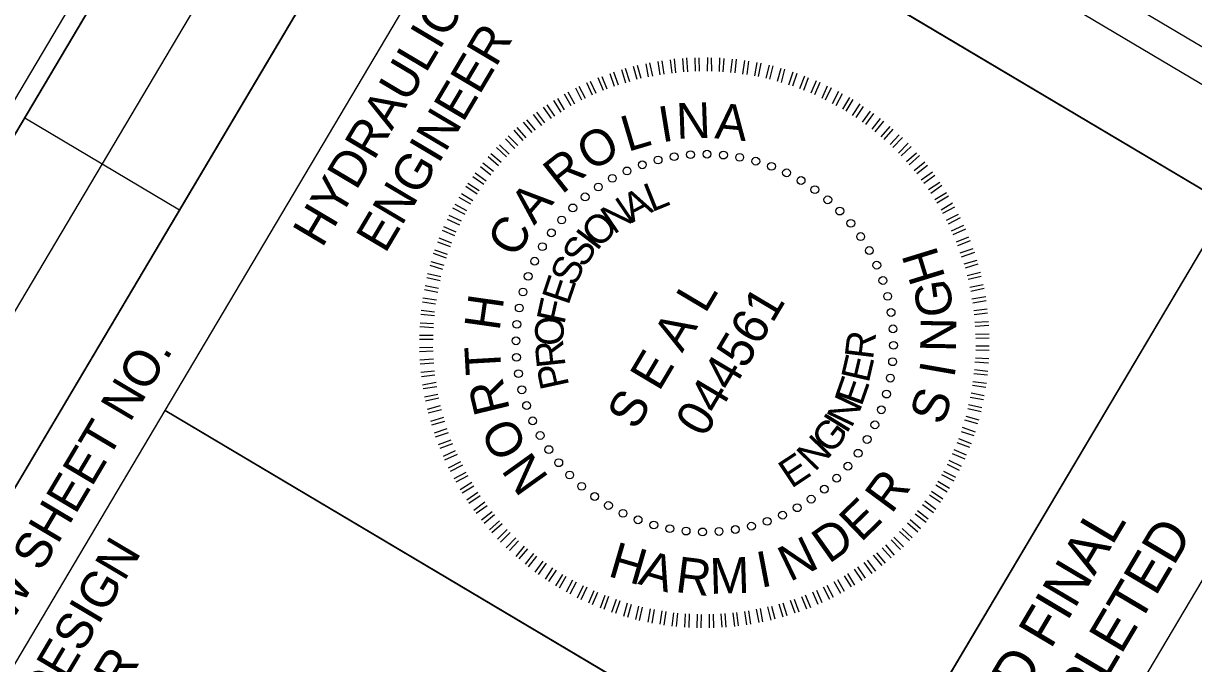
# Model space of a CAD drawing. Extents: x 2137081 to 2142019, y 404041 to 411238.
# Drawn here: x 2141049.2 to 2141211.9, y 410874.6 to 410963.6 of the extents above; entities that cross this region are included whole.
import ezdxf

# ---------------------------------------------------------------- set-up
doc = ezdxf.new("R2010")
doc.units = 0
for name, color, linetype in [('Old_Level_2', 7, 'Continuous'), ('Sheet Clip Boundary CELL', 7, 'Continuous'), ('Sheet Plan And Profile CELL', 7, 'Continuous'), ('Sheet Plot Border Inside CELL', 7, 'Continuous'), ('Sheet Plot Border Outside CELL', 7, 'Continuous'), ('Sheet Sticker Exception Certification CELL', 7, 'Continuous')]:
    doc.layers.add(name, color=color, linetype=linetype)

msp = doc.modelspace()

# ---------------------------------------------------------------- linework, layer by layer
at = {"layer": 'Old_Level_2'}
for p, q in [((2141137.73, 410956.43), (2141137.44, 410958.28)), ((2141138.28, 410956.5), (2141137.98, 410958.34)), ((2141139.36, 410956.63), (2141139.13, 410958.5)), ((2141139.9, 410956.7), (2141139.7, 410958.61)), ((2141140.99, 410956.84), (2141140.86, 410958.7)), ((2141141.54, 410956.84), (2141141.4, 410958.76)), ((2141142.64, 410956.91), (2141142.59, 410958.79)), ((2141143.2, 410956.91), (2141143.15, 410958.79)), ((2141144.28, 410956.94), (2141144.33, 410958.81)), ((2141144.88, 410956.92), (2141144.86, 410958.77)), ((2141145.95, 410956.85), (2141146.02, 410958.75)), ((2141146.48, 410956.81), (2141146.6, 410958.69)), ((2141147.55, 410956.73), (2141147.77, 410958.6)), ((2141148.13, 410956.67), (2141148.31, 410958.57)), ((2141149.21, 410956.52), (2141149.5, 410958.42)), ((2141149.79, 410956.46), (2141150.05, 410958.31)), ((2141150.85, 410956.28), (2141151.18, 410958.14)), ((2141131.36, 410954.8), (2141130.74, 410956.57)), ((2141131.91, 410954.98), (2141131.25, 410956.77)), ((2141132.92, 410955.27), (2141132.39, 410957.09)), ((2141133.47, 410955.45), (2141132.9, 410957.29)), ((2141134.51, 410955.78), (2141134.01, 410957.58)), ((2141135.07, 410955.89), (2141134.58, 410957.69)), ((2141136.1, 410956.12), (2141135.74, 410957.95)), ((2141136.67, 410956.23), (2141136.26, 410958.08)), ((2141151.4, 410956.17), (2141151.73, 410958.04)), ((2141152.44, 410955.95), (2141152.89, 410957.74)), ((2141152.96, 410955.8), (2141153.44, 410957.64)), ((2141154.02, 410955.51), (2141154.53, 410957.32)), ((2141154.58, 410955.34), (2141155.06, 410957.18)), ((2141155.61, 410955.01), (2141156.19, 410956.84)), ((2141156.14, 410954.86), (2141156.74, 410956.63)), ((2141128.29, 410953.57), (2141127.53, 410955.3)), ((2141128.82, 410953.81), (2141128.04, 410955.5)), ((2141129.84, 410954.21), (2141129.11, 410955.98)), ((2141130.35, 410954.41), (2141129.66, 410956.15)), ((2141157.14, 410954.49), (2141157.81, 410956.27)), ((2141157.69, 410954.28), (2141158.35, 410956.06)), ((2141158.69, 410953.91), (2141159.44, 410955.64)), ((2141159.21, 410953.66), (2141159.96, 410955.38)), ((2141160.21, 410953.18), (2141160.99, 410954.88)), ((2141125.35, 410952.08), (2141124.43, 410953.74)), ((2141125.84, 410952.35), (2141124.93, 410954)), ((2141126.82, 410952.88), (2141125.98, 410954.55)), ((2141127.35, 410953.12), (2141126.47, 410954.81)), ((2141160.68, 410952.95), (2141161.54, 410954.67)), ((2141161.66, 410952.43), (2141162.55, 410954.12)), ((2141162.17, 410952.17), (2141163.05, 410953.83)), ((2141163.08, 410951.64), (2141164.06, 410953.28)), ((2141122.58, 410950.33), (2141121.51, 410951.91)), ((2141123.05, 410950.66), (2141121.99, 410952.24)), ((2141123.95, 410951.24), (2141122.95, 410952.83)), ((2141124.4, 410951.53), (2141123.47, 410953.14)), ((2141163.57, 410951.34), (2141164.55, 410952.99)), ((2141164.46, 410950.76), (2141165.52, 410952.36)), ((2141164.95, 410950.47), (2141165.99, 410952.03)), ((2141120.4, 410948.72), (2141119.19, 410950.16)), ((2141121.24, 410949.39), (2141120.09, 410950.91)), ((2141121.68, 410949.75), (2141120.56, 410951.24)), ((2141165.85, 410949.82), (2141166.93, 410951.36)), ((2141166.28, 410949.51), (2141167.4, 410951.02)), ((2141167.18, 410948.87), (2141168.34, 410950.35)), ((2141167.62, 410948.49), (2141168.78, 410949.98)), ((2141118.66, 410947.3), (2141117.43, 410948.7)), ((2141119.1, 410947.65), (2141117.83, 410949.08)), ((2141119.92, 410948.39), (2141118.72, 410949.83)), ((2141168.43, 410947.79), (2141169.67, 410949.23)), ((2141168.84, 410947.44), (2141170.08, 410948.88)), ((2141117.49, 410946.16), (2141116.19, 410947.54)), ((2141117.9, 410946.58), (2141116.58, 410947.92)), ((2141169.69, 410946.71), (2141170.94, 410948.08)), ((2141170.07, 410946.32), (2141171.39, 410947.71)), ((2141170.83, 410945.53), (2141172.19, 410946.9)), ((2141115.61, 410944.21), (2141114.17, 410945.45)), ((2141116.35, 410945), (2141114.96, 410946.32)), ((2141116.7, 410945.4), (2141115.36, 410946.7)), ((2141171.2, 410945.14), (2141172.59, 410946.44)), ((2141171.96, 410944.36), (2141173.36, 410945.59)), ((2141172.32, 410943.92), (2141173.74, 410945.2)), ((2141114.19, 410942.49), (2141112.71, 410943.65)), ((2141114.53, 410942.96), (2141113.04, 410944.12)), ((2141115.23, 410943.77), (2141113.79, 410945.01)), ((2141173.01, 410943.12), (2141174.5, 410944.3)), ((2141173.37, 410942.69), (2141174.85, 410943.87)), ((2141113.2, 410941.18), (2141111.66, 410942.26)), ((2141113.53, 410941.65), (2141112, 410942.73)), ((2141174.01, 410941.8), (2141175.58, 410942.94)), ((2141174.37, 410941.37), (2141175.87, 410942.49)), ((2141112.28, 410939.83), (2141110.68, 410940.89)), ((2141112.55, 410940.29), (2141110.99, 410941.32)), ((2141175.02, 410940.49), (2141176.57, 410941.51)), ((2141175.32, 410939.97), (2141176.86, 410941.06)), ((2141111.39, 410938.42), (2141109.78, 410939.37)), ((2141111.68, 410938.91), (2141110.07, 410939.86)), ((2141175.9, 410939.07), (2141177.5, 410940.07)), ((2141176.19, 410938.62), (2141177.79, 410939.62)), ((2141176.75, 410937.67), (2141178.36, 410938.61)), ((2141110.6, 410936.99), (2141108.9, 410937.89)), ((2141110.85, 410937.51), (2141109.19, 410938.38)), ((2141177.01, 410937.18), (2141178.67, 410938.09)), ((2141177.5, 410936.22), (2141179.17, 410937.07)), ((2141109.85, 410935.54), (2141108.14, 410936.33)), ((2141110.1, 410936.06), (2141108.39, 410936.85)), ((2141177.77, 410935.73), (2141179.44, 410936.58)), ((2141178.23, 410934.73), (2141179.92, 410935.51)), ((2141108.74, 410933.02), (2141106.99, 410933.73)), ((2141109.18, 410934.04), (2141107.45, 410934.79)), ((2141109.37, 410934.54), (2141107.64, 410935.29)), ((2141178.43, 410934.22), (2141180.18, 410935.02)), ((2141178.9, 410933.22), (2141180.64, 410933.91)), ((2141108.55, 410932.52), (2141106.78, 410933.18)), ((2141179.09, 410932.71), (2141180.84, 410933.41)), ((2141179.43, 410931.68), (2141181.23, 410932.28)), ((2141108.01, 410930.95), (2141106.21, 410931.57)), ((2141108.16, 410931.47), (2141106.4, 410932.07)), ((2141179.6, 410931.13), (2141181.43, 410931.77)), ((2141179.96, 410930.14), (2141181.78, 410930.67)), ((2141107.51, 410929.35), (2141105.72, 410929.91)), ((2141107.68, 410929.92), (2141105.87, 410930.44)), ((2141180.14, 410929.59), (2141181.92, 410930.15)), ((2141180.4, 410928.54), (2141182.24, 410929.01)), ((2141107.14, 410927.79), (2141105.28, 410928.22)), ((2141107.24, 410928.34), (2141105.38, 410928.77)), ((2141180.54, 410928.01), (2141182.35, 410928.44)), ((2141180.78, 410926.92), (2141182.61, 410927.28)), ((2141106.79, 410926.16), (2141104.94, 410926.53)), ((2141106.89, 410926.71), (2141105.05, 410927.08)), ((2141180.89, 410926.36), (2141182.75, 410926.76)), ((2141181.05, 410925.31), (2141182.97, 410925.63)), ((2141106.5, 410924.55), (2141104.65, 410924.81)), ((2141106.6, 410925.1), (2141104.71, 410925.38)), ((2141181.16, 410924.75), (2141183.03, 410925.08)), ((2141106.32, 410922.93), (2141104.42, 410923.11)), ((2141106.35, 410923.46), (2141104.48, 410923.68)), ((2141181.3, 410923.66), (2141183.16, 410923.89)), ((2141181.37, 410923.12), (2141183.23, 410923.35)), ((2141106.18, 410921.28), (2141104.29, 410921.4)), ((2141106.21, 410921.82), (2141104.33, 410921.93)), ((2141181.46, 410922.06), (2141183.36, 410922.16)), ((2141181.51, 410921.48), (2141183.39, 410921.64)), ((2141106.14, 410920.19), (2141104.25, 410920.2)), ((2141106.14, 410919.63), (2141104.25, 410919.64)), ((2141181.54, 410920.4), (2141183.45, 410920.44)), ((2141181.58, 410919.82), (2141183.45, 410919.88)), ((2141106.11, 410918.54), (2141104.23, 410918.48)), ((2141106.17, 410918), (2141104.24, 410917.92)), ((2141181.57, 410918.77), (2141183.46, 410918.76)), ((2141181.57, 410918.21), (2141183.44, 410918.16)), ((2141106.2, 410916.92), (2141104.32, 410916.75)), ((2141106.25, 410916.34), (2141104.33, 410916.2)), ((2141181.47, 410916.54), (2141183.35, 410916.42)), ((2141181.54, 410917.11), (2141183.42, 410917)), ((2141106.32, 410915.24), (2141104.44, 410915.07)), ((2141106.39, 410914.69), (2141104.52, 410914.46)), ((2141181.33, 410914.9), (2141183.23, 410914.72)), ((2141181.4, 410915.47), (2141183.27, 410915.25)), ((2141106.55, 410913.65), (2141104.68, 410913.31)), ((2141106.66, 410913.08), (2141104.75, 410912.77)), ((2141181.11, 410913.3), (2141183, 410913.01)), ((2141181.19, 410913.81), (2141183.06, 410913.59)), ((2141106.8, 410912), (2141104.96, 410911.64)), ((2141106.93, 410911.48), (2141105.07, 410911.07)), ((2141180.8, 410911.65), (2141182.66, 410911.32)), ((2141180.93, 410912.24), (2141182.77, 410911.87)), ((2141107.13, 410910.41), (2141105.33, 410909.92)), ((2141107.31, 410909.86), (2141105.47, 410909.39)), ((2141180.47, 410910.06), (2141182.33, 410909.62)), ((2141180.57, 410910.61), (2141182.43, 410910.18)), ((2141107.57, 410908.81), (2141105.79, 410908.25)), ((2141107.75, 410908.26), (2141105.93, 410907.72)), ((2141180.03, 410908.48), (2141181.84, 410907.96)), ((2141180.18, 410909.01), (2141181.99, 410908.49)), ((2141108.04, 410907.25), (2141106.28, 410906.62)), ((2141108.26, 410906.68), (2141106.45, 410906.08)), ((2141179.53, 410906.88), (2141181.32, 410906.32)), ((2141179.7, 410907.45), (2141181.5, 410906.83)), ((2141108.62, 410905.68), (2141106.87, 410904.99)), ((2141108.82, 410905.17), (2141107.07, 410904.48)), ((2141178.95, 410905.34), (2141180.72, 410904.67)), ((2141179.16, 410905.88), (2141180.93, 410905.21)), ((2141109.22, 410904.16), (2141107.53, 410903.38)), ((2141109.48, 410903.67), (2141107.73, 410902.87)), ((2141177.86, 410902.86), (2141179.54, 410902.03)), ((2141178.32, 410903.81), (2141180.05, 410903.07)), ((2141178.53, 410904.36), (2141180.26, 410903.61)), ((2141109.95, 410902.67), (2141108.25, 410901.78)), ((2141110.21, 410902.17), (2141108.51, 410901.29)), ((2141110.68, 410901.17), (2141109.04, 410900.3)), ((2141177.09, 410901.37), (2141178.75, 410900.5)), ((2141177.61, 410902.34), (2141179.29, 410901.51)), ((2141110.97, 410900.72), (2141109.31, 410899.81)), ((2141111.52, 410899.78), (2141109.92, 410898.78)), ((2141176.3, 410899.94), (2141177.91, 410898.99)), ((2141176.82, 410900.91), (2141178.52, 410900.02)), ((2141111.79, 410899.29), (2141110.19, 410898.29)), ((2141112.37, 410898.39), (2141110.83, 410897.3)), ((2141175.13, 410898.07), (2141176.69, 410897.03)), ((2141175.43, 410898.56), (2141176.99, 410897.53)), ((2141176.01, 410899.45), (2141177.61, 410898.49)), ((2141112.7, 410897.91), (2141111.12, 410896.85)), ((2141113.34, 410897.03), (2141111.82, 410895.87)), ((2141113.67, 410896.55), (2141112.13, 410895.46)), ((2141174.18, 410896.74), (2141175.69, 410895.62)), ((2141174.51, 410897.21), (2141176.02, 410896.09)), ((2141114.34, 410895.71), (2141112.86, 410894.53)), ((2141114.7, 410895.28), (2141113.22, 410894.09)), ((2141173.18, 410895.44), (2141174.67, 410894.28)), ((2141173.49, 410895.87), (2141174.98, 410894.71)), ((2141115.37, 410894.43), (2141113.97, 410893.2)), ((2141115.75, 410894.04), (2141114.32, 410892.77)), ((2141116.44, 410893.24), (2141115.1, 410891.92)), ((2141171.36, 410893.4), (2141172.75, 410892.08)), ((2141172.11, 410894.19), (2141173.54, 410892.94)), ((2141172.48, 410894.63), (2141173.92, 410893.39)), ((2141116.86, 410892.82), (2141115.52, 410891.5)), ((2141117.65, 410892.08), (2141116.32, 410890.69)), ((2141118.03, 410891.69), (2141116.77, 410890.32)), ((2141169.81, 410891.82), (2141171.13, 410890.48)), ((2141170.2, 410892.2), (2141171.52, 410890.86)), ((2141170.99, 410892.96), (2141172.36, 410891.7)), ((2141118.81, 410890.94), (2141117.63, 410889.52)), ((2141119.26, 410890.57), (2141118.04, 410889.17)), ((2141120.09, 410889.9), (2141118.93, 410888.42)), ((2141167.79, 410890.01), (2141168.99, 410888.57)), ((2141168.59, 410890.7), (2141169.82, 410889.3)), ((2141169.05, 410891.1), (2141170.25, 410889.66)), ((2141120.53, 410889.53), (2141119.37, 410888.04)), ((2141121.41, 410888.84), (2141120.29, 410887.33)), ((2141121.86, 410888.57), (2141120.76, 410887)), ((2141166.03, 410888.65), (2141167.15, 410887.15)), ((2141166.47, 410889.01), (2141167.63, 410887.48)), ((2141167.31, 410889.68), (2141168.52, 410888.24)), ((2141122.76, 410887.93), (2141121.7, 410886.33)), ((2141123.23, 410887.59), (2141122.19, 410886.04)), ((2141124.11, 410887.01), (2141123.16, 410885.41)), ((2141124.61, 410886.72), (2141123.65, 410885.11)), ((2141163.28, 410886.83), (2141164.24, 410885.26)), ((2141163.73, 410887.12), (2141164.73, 410885.52)), ((2141164.66, 410887.74), (2141165.73, 410886.16)), ((2141165.13, 410888.07), (2141166.2, 410886.49)), ((2141125.54, 410886.22), (2141124.64, 410884.53)), ((2141126.03, 410885.93), (2141125.16, 410884.27)), ((2141127, 410885.41), (2141126.17, 410883.73)), ((2141127.51, 410885.22), (2141126.69, 410883.48)), ((2141160.36, 410885.28), (2141161.24, 410883.58)), ((2141160.89, 410885.52), (2141161.74, 410883.85)), ((2141161.85, 410886.01), (2141162.78, 410884.4)), ((2141162.36, 410886.32), (2141163.28, 410884.66)), ((2141128.5, 410884.74), (2141127.75, 410883.01)), ((2141129.02, 410884.49), (2141128.27, 410882.76)), ((2141130, 410884.08), (2141129.36, 410882.34)), ((2141130.53, 410883.93), (2141129.9, 410882.13)), ((2141131.57, 410883.53), (2141130.95, 410881.73)), ((2141132.08, 410883.35), (2141131.52, 410881.56)), ((2141155.8, 410883.42), (2141156.42, 410881.65)), ((2141156.35, 410883.59), (2141156.97, 410881.83)), ((2141157.34, 410883.95), (2141158.05, 410882.25)), ((2141157.87, 410884.19), (2141158.6, 410882.42)), ((2141158.89, 410884.59), (2141159.64, 410882.86)), ((2141159.42, 410884.83), (2141160.18, 410883.1)), ((2141133.1, 410883.01), (2141132.63, 410881.18)), ((2141133.67, 410882.84), (2141133.15, 410881.03)), ((2141134.68, 410882.58), (2141134.27, 410880.76)), ((2141135.23, 410882.47), (2141134.8, 410880.61)), ((2141136.31, 410882.22), (2141135.98, 410880.36)), ((2141136.86, 410882.12), (2141136.54, 410880.25)), ((2141137.92, 410881.94), (2141137.66, 410880.09)), ((2141138.5, 410881.87), (2141138.21, 410879.98)), ((2141139.56, 410881.69), (2141139.34, 410879.81)), ((2141147.79, 410881.65), (2141148.02, 410879.79)), ((2141148.33, 410881.72), (2141148.56, 410879.86)), ((2141149.41, 410881.86), (2141149.71, 410880.01)), ((2141149.98, 410881.97), (2141150.27, 410880.12)), ((2141151.05, 410882.17), (2141151.41, 410880.34)), ((2141151.61, 410882.28), (2141151.95, 410880.41)), ((2141152.64, 410882.51), (2141153.11, 410880.67)), ((2141153.2, 410882.62), (2141153.66, 410880.84)), ((2141154.21, 410882.91), (2141154.77, 410881.13)), ((2141154.76, 410883.08), (2141155.32, 410881.3)), ((2141140.14, 410881.63), (2141139.94, 410879.79)), ((2141141.2, 410881.55), (2141141.09, 410879.67)), ((2141141.74, 410881.51), (2141141.69, 410879.65)), ((2141142.83, 410881.47), (2141142.82, 410879.58)), ((2141143.43, 410881.45), (2141143.38, 410879.59)), ((2141144.51, 410881.48), (2141144.54, 410879.57)), ((2141145.07, 410881.49), (2141145.12, 410879.61)), ((2141146.14, 410881.52), (2141146.27, 410879.66)), ((2141146.68, 410881.58), (2141146.85, 410879.7))]:
    msp.add_line(p, q, dxfattribs=at)
for centre in [(2141137.42, 410944.58), (2141139.66, 410945.04), (2141141.93, 410945.32), (2141144.22, 410945.39), (2141146.51, 410945.26), (2141148.77, 410944.94), (2141133.1, 410943.06), (2141135.23, 410943.91), (2141151, 410944.41), (2141153.18, 410943.7), (2141131.06, 410942.03), (2141155.28, 410942.8), (2141157.3, 410941.72), (2141129.11, 410940.82), (2141159.22, 410940.46), (2141127.28, 410939.45), (2141161.01, 410939.05), (2141125.57, 410937.92), (2141162.68, 410937.48), (2141124.01, 410936.25), (2141164.21, 410935.78), (2141122.59, 410934.45), (2141165.58, 410933.94), (2141121.34, 410932.54), (2141166.79, 410932), (2141120.26, 410930.52), (2141167.82, 410929.96), (2141119.36, 410928.42), (2141168.67, 410927.83), (2141118.64, 410926.24), (2141169.34, 410925.64), (2141118.12, 410924.01), (2141169.81, 410923.4), (2141117.79, 410921.75), (2141170.08, 410921.12), (2141117.67, 410919.46), (2141170.15, 410918.84), (2141117.74, 410917.17), (2141170.02, 410916.55), (2141118.01, 410914.9), (2141169.7, 410914.28), (2141118.48, 410912.66), (2141169.18, 410912.06), (2141119.14, 410910.47), (2141168.46, 410909.88), (2141119.99, 410908.34), (2141167.56, 410907.78), (2141121.03, 410906.3), (2141166.48, 410905.76), (2141122.23, 410904.35), (2141123.61, 410902.52), (2141165.23, 410903.84), (2141125.13, 410900.81), (2141163.81, 410902.04), (2141126.8, 410899.25), (2141162.24, 410900.37), (2141128.6, 410897.83), (2141158.7, 410897.47), (2141160.54, 410898.85), (2141130.52, 410896.58), (2141156.76, 410896.27), (2141132.54, 410895.5), (2141134.64, 410894.6), (2141152.59, 410894.38), (2141154.72, 410895.23), (2141136.82, 410893.88), (2141139.05, 410893.36), (2141141.31, 410893.03), (2141143.6, 410892.91), (2141145.89, 410892.98), (2141148.16, 410893.25), (2141150.4, 410893.72)]:
    msp.add_circle(centre, 0.543, dxfattribs=at)
at = {"layer": 'Sheet Clip Boundary CELL'}
msp.add_lwpolyline([(2140795, 409444.32), (2141473.2, 410586.96), (2141453.94, 410598.39), (2141513.05, 410697.97), (2141213, 410886.12), (2141134.78, 410754.33), (2141040.49, 410810.3), (2140938.2, 410637.97), (2140883.25, 410670.58), (2140322.04, 409725.04)], close=True, dxfattribs=at)
at = {"layer": 'Sheet Plan And Profile CELL'}
for p, q in [((2140996.33, 410836.51), (2141098.43, 411008.54)), ((2141007.08, 410830.13), (2141109.18, 411002.16)), ((2141049.4, 410950.42), (2141070.9, 410937.66)), ((2141068.89, 410909.79), (2141165.59, 410852.39))]:
    msp.add_line(p, q, dxfattribs=at)
for points in [[(2141087.64, 411014.95), (2140322.04, 409725.04), (2141224.97, 409189.12), (2141990.57, 410479.02)], [(2140985.54, 410842.92), (2141087.64, 411014.95), (2141109.18, 411002.16), (2141007.08, 410830.13)], [(2141068.89, 410909.79), (2141119.93, 410995.78), (2141216.67, 410938.36), (2141165.63, 410852.37)], [(2141017.83, 410823.75), (2141068.89, 410909.79), (2141165.63, 410852.37), (2141114.57, 410766.33)]]:
    msp.add_lwpolyline(points, close=True, dxfattribs=at)
at = {"layer": 'Sheet Plot Border Inside CELL'}
msp.add_lwpolyline([(2141148.77, 409055.84), (2141999.1, 410488.49), (2141091.87, 411026.97), (2140241.54, 409594.32)], close=True, dxfattribs=at)
at = {"layer": 'Sheet Plot Border Outside CELL'}
msp.add_lwpolyline([(2141159.33, 409034.46), (2142018.6, 410482.16), (2141076.97, 411041.05), (2140217.7, 409593.35)], close=True, dxfattribs=at)
at = {"layer": 'Sheet Sticker Exception Certification CELL'}
for p, q in [((2141114.57, 410766.33), (2141216.67, 410938.35)), ((2141236.88, 410926.35), (2141134.78, 410754.33))]:
    msp.add_line(p, q, dxfattribs=at)

# ---------------------------------------------------------------- texts
at = {"layer": 'Old_Level_2'}
for s, height, rotation, p in [('I', 4.96, 9.2695, (2141137.93, 410947.01)), ('N', 4.96, 2.004, (2141140.01, 410947.5)), ('A', 4.96, 354.7385, (2141145.2, 410947.6)), ('L', 4.96, 16.535, (2141133.2, 410945.69)), ('O', 4.96, 31.066, (2141128.08, 410942.88)), ('R', 4.96, 38.3315, (2141124.03, 410939.72)), ('A', 4.96, 49.0114, (2141120.19, 410935.42)), ('A', 3.98, 28.0564, (2141133.8, 410935.81)), ('L', 3.98, 21.8725, (2141136.53, 410937.31)), ('N', 3.98, 34.2403, (2141131.25, 410934.15)), ('O', 3.98, 46.6081, (2141129.24, 410932.17)), ('C', 4.96, 60.128, (2141117.73, 410930.8)), ('S', 3.98, 58.9759, (2141127.24, 410929.45)), ('I', 3.98, 52.792, (2141128.91, 410931.8)), ('H', 4.98, 107.0795, (2141177.39, 410928.25)), ('S', 3.98, 65.1598, (2141125.87, 410926.87)), ('E', 3.98, 71.3437, (2141124.95, 410924.29)), ('G', 4.98, 98.0795, (2141178.54, 410923.14)), ('H', 4.96, 81.9245, (2141115.37, 410920.73)), ('S E A L', 4.98, 59.3093, (2141134.34, 410906.88)), ('044561', 4.98, 59.3093, (2141143.86, 410905.84)), ('F', 3.98, 77.5277, (2141124.37, 410921.62)), ('O', 3.98, 89.8955, (2141124.3, 410918.77)), ('N', 4.98, 89.0795, (2141178.82, 410917.87)), ('R', 3.98, 96.0794, (2141124.57, 410915.94)), ('R', 3.98, 83.0449, (2141167.29, 410916.77)), ('T', 4.96, 93.2995, (2141115.66, 410914.82)), ('E', 3.98, 76.861, (2141166.69, 410913.5)), ('P', 3.98, 102.2633, (2141125.08, 410913.24)), ('I', 4.98, 80.0795, (2141178.57, 410914.19)), ('R', 4.96, 103.721, (2141116.85, 410909.88)), ('E', 3.98, 70.6771, (2141165.7, 410910.24)), ('S', 4.98, 71.0795, (2141176.99, 410907.58)), ('N', 3.98, 64.4932, (2141164.3, 410907.23)), ('I', 3.98, 58.3093, (2141163.6, 410906.42)), ('O', 4.96, 118.252, (2141119.39, 410904.69)), ('G', 3.98, 52.1254, (2141161.57, 410903.56)), ('N', 3.98, 45.9415, (2141159.2, 410901.17)), ('N', 4.96, 125.5175, (2141122.33, 410900.44)), ('E', 3.98, 33.5736, (2141155.94, 410898.87)), ('R', 4.98, 53.4897, (2141169.86, 410895.29)), ('E', 4.98, 44.0834, (2141165.62, 410891.37)), ('D', 4.98, 35.4103, (2141161.16, 410888.4)), ('H', 4.98, 343.7672, (2141130.3, 410886.81)), ('N', 4.98, 25.6986, (2141155.71, 410885.92)), ('A', 4.98, 343.7672, (2141134.51, 410885.71)), ('I', 4.98, 10.7672, (2141151.67, 410885.13)), ('R', 4.98, 352.7672, (2141139.7, 410884.59)), ('M', 4.98, 1.7672, (2141144.66, 410884.29))]:
    msp.add_text(s, height=height, rotation=rotation, dxfattribs=at).set_placement(p)
at = {"layer": 'Sheet Plan And Profile CELL'}
for s, height, p in [('HYDRAULICS', 5, (2141090.71, 410932.25)), ('ENGINEER', 5, (2141099.49, 410931.46)), ('R/W SHEET NO.', 5.0001, (2141044.08, 410874.45)), ('ROADWAY DESIGN', 5.0001, (2141034, 410836.71)), ('ENGINEER', 5, (2141047.62, 410844.85))]:
    msp.add_text(s, height=height, rotation=59.3093, dxfattribs=at).set_placement(p)
at = {"layer": 'Sheet Sticker Exception Certification CELL'}
for s, p in [('DOCUMENT NOT CONSIDERED FINAL', (2141134.22, 410779.17)), ('UNLESS ALL SIGNATURES COMPLETED', (2141139.2, 410770.32))]:
    msp.add_text(s, height=5.5, rotation=59.3093, dxfattribs=at).set_placement(p)

doc.saveas('drawing.dxf')
